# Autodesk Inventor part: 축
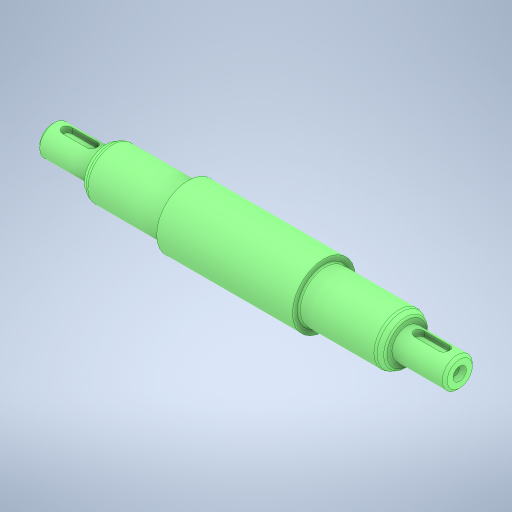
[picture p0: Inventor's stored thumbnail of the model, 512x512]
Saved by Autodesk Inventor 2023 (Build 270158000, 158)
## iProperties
Created: 2026-03
Part Number: 축
Material: 강철, 탄소
Document SubType Name: Modeling
Designer: home
Density: 7.85 g/cm^3
Appearance: 기본값
Author: jhkim
Sending System: Autodesk Inventor 2026
Preprocessor: ST-DEVELOPER v20.1
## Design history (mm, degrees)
feature "솔리드1"
node "솔리드2"
